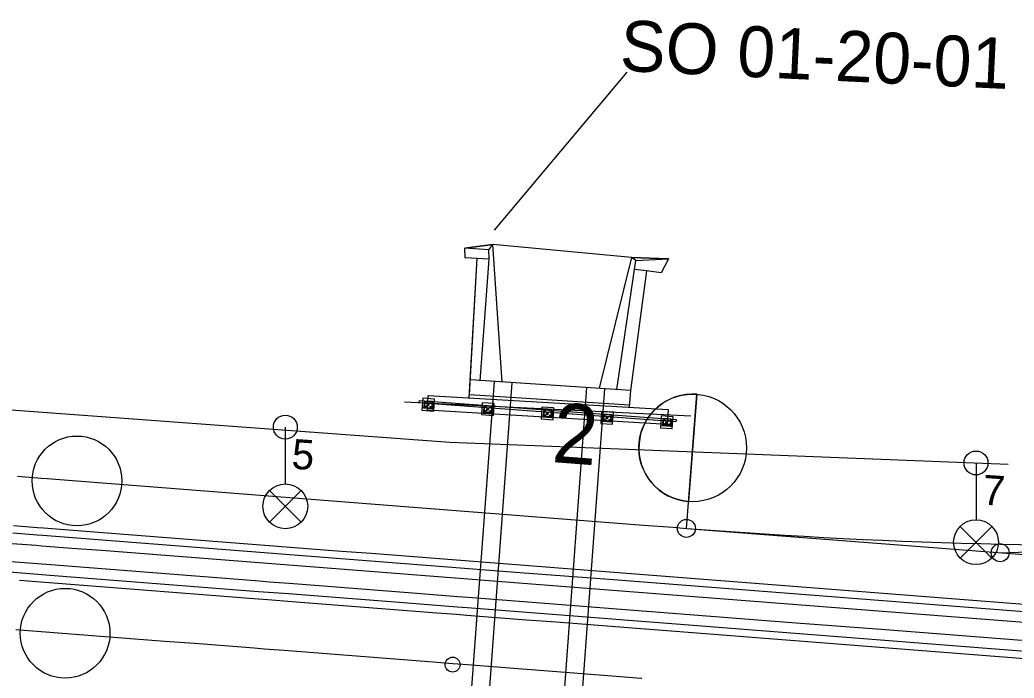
# Model space of a CAD drawing. Extents: x -669628 to -669207, y -977198 to -977075.
# Drawn here: x -669490.41 to -669457.17, y -977145.94 to -977123.92 of the extents above; entities that cross this region are included whole.
import ezdxf

# ---------------------------------------------------------------- set-up
doc = ezdxf.new("R2010")
doc.units = 0
for name, color, linetype in [('_PS_SO_číslo', 7, 'Continuous'), ('SO 01-20-01', 7, 'Continuous'), ('SO 01-20-01_Demolice', 7, 'Continuous'), ('SO 01-86-01', 7, 'Continuous'), ('SO 11-10-01', 7, 'Continuous'), ('SO 11-12-01', 7, 'Continuous')]:
    doc.layers.add(name, color=color, linetype=linetype)

# ---------------------------------------------------------------- blocks, each defined once
blk = doc.blocks.new('POINT_DISPLAY')
blk.add_line((0, 0), (0, 0))

msp = doc.modelspace()

# ---------------------------------------------------------------- linework, layer by layer
at = {"layer": '_PS_SO_číslo'}
msp.add_line((-669470.117, -977125.676), (-669474.557, -977130.959), dxfattribs=at)
at = {"layer": 'SO 01-20-01'}
for p, q in [((-669475.537, -977131.559), (-669474.597, -977131.44)), ((-669474.597, -977131.44), (-669475.537, -977131.559)), ((-669474.727, -977131.621), (-669474.597, -977131.44)), ((-669474.289, -977136.037), (-669474.597, -977131.44)), ((-669469.961, -977131.873), (-669474.597, -977131.44)), ((-669475.524, -977131.878), (-669475.537, -977131.559)), ((-669475.524, -977131.878), (-669475.537, -977131.559)), ((-669474.727, -977131.621), (-669475.537, -977131.559)), ((-669474.725, -977131.927), (-669474.727, -977131.621)), ((-669475.124, -977131.902), (-669475.524, -977131.878)), ((-669475.124, -977131.902), (-669475.524, -977131.878)), ((-669475.385, -977136.563), (-669475.124, -977131.902)), ((-669475.38, -977136.467), (-669475.124, -977131.902)), ((-669474.725, -977131.927), (-669475.124, -977131.902)), ((-669475.019, -977135.992), (-669474.725, -977131.927)), ((-669469.961, -977131.873), (-669471.044, -977136.247)), ((-669469.961, -977131.873), (-669468.725, -977131.916)), ((-669469.82, -977131.972), (-669469.961, -977131.873)), ((-669468.725, -977131.916), (-669469.961, -977131.873)), ((-669469.86, -977132.27), (-669469.82, -977131.972)), ((-669469.82, -977131.972), (-669468.725, -977131.916)), ((-669468.725, -977131.916), (-669468.968, -977132.39)), ((-669468.725, -977131.916), (-669468.968, -977132.39)), ((-669470.456, -977136.286), (-669469.86, -977132.27)), ((-669469.464, -977132.323), (-669469.998, -977136.315)), ((-669469.464, -977132.323), (-669469.86, -977132.27)), ((-669468.968, -977132.39), (-669469.464, -977132.323)), ((-669468.968, -977132.39), (-669469.464, -977132.323)), ((-669475.576, -977150.04), (-669474.546, -977136.022)), ((-669469.998, -977136.315), (-669475.348, -977135.968)), ((-669474.959, -977149.839), (-669473.947, -977136.066)), ((-669470.034, -977136.814), (-669475.38, -977136.467)), ((-669472.47, -977150.083), (-669471.452, -977136.221)), ((-669471.836, -977149.643), (-669470.854, -977136.265)), ((-669469.998, -977136.315), (-669470.039, -977136.876)), ((-669476.885, -977136.673), (-669476.918, -977136.916)), ((-669476.871, -977136.689), (-669476.886, -977136.889)), ((-669476.615, -977136.693), (-669476.885, -977136.673)), ((-669476.871, -977136.689), (-669476.885, -977136.673)), ((-669476.631, -977136.707), (-669476.871, -977136.689)), ((-669476.854, -977136.731), (-669476.814, -977136.734)), ((-669476.844, -977136.872), (-669476.841, -977136.832)), ((-669476.835, -977136.752), (-669476.832, -977136.712)), ((-669476.795, -977136.755), (-669476.801, -977136.835)), ((-669476.719, -977136.801), (-669476.798, -977136.795)), ((-669476.716, -977136.761), (-669476.795, -977136.755)), ((-669476.788, -977136.768), (-669476.793, -977136.827)), ((-669476.724, -977136.768), (-669476.783, -977136.764)), ((-669476.756, -977136.758), (-669476.761, -977136.838)), ((-669476.694, -977136.742), (-669476.654, -977136.745)), ((-669476.676, -977136.764), (-669476.673, -977136.724)), ((-669476.631, -977136.707), (-669476.646, -977136.906)), ((-669476.631, -977136.707), (-669476.615, -977136.693)), ((-669476.615, -977136.693), (-669476.618, -977136.938)), ((-669474.89, -977136.82), (-669474.923, -977137.063)), ((-669474.621, -977136.839), (-669474.89, -977136.82)), ((-669474.876, -977136.836), (-669474.89, -977136.82)), ((-669476.886, -977136.889), (-669476.918, -977136.916)), ((-669476.618, -977136.938), (-669476.918, -977136.916)), ((-669476.646, -977136.906), (-669476.886, -977136.889)), ((-669476.863, -977136.85), (-669476.823, -977136.853)), ((-669476.703, -977136.862), (-669476.663, -977136.865)), ((-669476.685, -977136.883), (-669476.682, -977136.843)), ((-669476.646, -977136.906), (-669476.618, -977136.938)), ((-669474.891, -977137.035), (-669474.923, -977137.063)), ((-669474.624, -977137.085), (-669474.923, -977137.063)), ((-669474.876, -977136.836), (-669474.891, -977137.035)), ((-669474.652, -977137.053), (-669474.891, -977137.035)), ((-669474.637, -977136.853), (-669474.876, -977136.836)), ((-669474.868, -977136.997), (-669474.828, -977137)), ((-669474.859, -977136.877), (-669474.819, -977136.88)), ((-669474.85, -977137.018), (-669474.847, -977136.978)), ((-669474.841, -977136.899), (-669474.838, -977136.859)), ((-669474.801, -977136.901), (-669474.807, -977136.981)), ((-669474.724, -977136.947), (-669474.804, -977136.941)), ((-669474.721, -977136.907), (-669474.801, -977136.901)), ((-669474.794, -977136.915), (-669474.798, -977136.974)), ((-669474.73, -977136.915), (-669474.788, -977136.91)), ((-669474.761, -977136.904), (-669474.767, -977136.984)), ((-669474.708, -977137.009), (-669474.669, -977137.011)), ((-669474.7, -977136.889), (-669474.66, -977136.892)), ((-669474.69, -977137.03), (-669474.687, -977136.99)), ((-669474.681, -977136.91), (-669474.678, -977136.87)), ((-669474.637, -977136.853), (-669474.652, -977137.053)), ((-669474.652, -977137.053), (-669474.624, -977137.085)), ((-669474.637, -977136.853), (-669474.621, -977136.839)), ((-669474.621, -977136.839), (-669474.624, -977137.085)), ((-669472.895, -977136.966), (-669472.928, -977137.209)), ((-669472.882, -977136.982), (-669472.896, -977137.182)), ((-669472.626, -977136.986), (-669472.895, -977136.966)), ((-669472.882, -977136.982), (-669472.895, -977136.966)), ((-669472.642, -977137), (-669472.882, -977136.982)), ((-669472.873, -977137.143), (-669472.833, -977137.146)), ((-669472.865, -977137.024), (-669472.825, -977137.027)), ((-669472.855, -977137.165), (-669472.852, -977137.125)), ((-669472.846, -977137.045), (-669472.843, -977137.005)), ((-669472.806, -977137.048), (-669472.812, -977137.128)), ((-669472.729, -977137.094), (-669472.809, -977137.088)), ((-669472.726, -977137.054), (-669472.806, -977137.048)), ((-669472.799, -977137.062), (-669472.804, -977137.12)), ((-669472.735, -977137.061), (-669472.794, -977137.057)), ((-669472.766, -977137.051), (-669472.772, -977137.131)), ((-669472.714, -977137.155), (-669472.674, -977137.158)), ((-669472.705, -977137.035), (-669472.665, -977137.038)), ((-669472.695, -977137.176), (-669472.692, -977137.137)), ((-669472.687, -977137.057), (-669472.684, -977137.017)), ((-669472.642, -977137), (-669472.657, -977137.199)), ((-669472.642, -977137), (-669472.626, -977136.986)), ((-669472.626, -977136.986), (-669472.629, -977137.231)), ((-669470.901, -977137.113), (-669470.934, -977137.356)), ((-669470.887, -977137.129), (-669470.902, -977137.328)), ((-669470.632, -977137.133), (-669470.901, -977137.113)), ((-669470.887, -977137.129), (-669470.901, -977137.113)), ((-669470.648, -977137.146), (-669470.887, -977137.129)), ((-669470.851, -977137.192), (-669470.849, -977137.152)), ((-669470.692, -977137.203), (-669470.689, -977137.163)), ((-669470.648, -977137.146), (-669470.662, -977137.346)), ((-669470.648, -977137.146), (-669470.632, -977137.133)), ((-669470.632, -977137.133), (-669470.635, -977137.378)), ((-669472.896, -977137.182), (-669472.928, -977137.209)), ((-669472.629, -977137.231), (-669472.928, -977137.209)), ((-669472.657, -977137.199), (-669472.896, -977137.182)), ((-669472.657, -977137.199), (-669472.629, -977137.231)), ((-669470.902, -977137.328), (-669470.934, -977137.356)), ((-669470.635, -977137.378), (-669470.934, -977137.356)), ((-669470.662, -977137.346), (-669470.902, -977137.328)), ((-669470.879, -977137.29), (-669470.839, -977137.293)), ((-669470.87, -977137.17), (-669470.83, -977137.173)), ((-669470.86, -977137.311), (-669470.857, -977137.271)), ((-669470.812, -977137.195), (-669470.817, -977137.274)), ((-669470.735, -977137.24), (-669470.815, -977137.234)), ((-669470.732, -977137.2), (-669470.812, -977137.195)), ((-669470.805, -977137.208), (-669470.809, -977137.267)), ((-669470.74, -977137.208), (-669470.799, -977137.203)), ((-669470.772, -977137.197), (-669470.778, -977137.277)), ((-669470.719, -977137.302), (-669470.679, -977137.305)), ((-669470.71, -977137.182), (-669470.67, -977137.185)), ((-669470.701, -977137.323), (-669470.698, -977137.283)), ((-669470.662, -977137.346), (-669470.635, -977137.378)), ((-669468.906, -977137.259), (-669468.939, -977137.503)), ((-669468.907, -977137.475), (-669468.939, -977137.503)), ((-669468.892, -977137.275), (-669468.907, -977137.475)), ((-669468.668, -977137.492), (-669468.907, -977137.475)), ((-669468.637, -977137.279), (-669468.906, -977137.259)), ((-669468.892, -977137.275), (-669468.906, -977137.259)), ((-669468.653, -977137.293), (-669468.892, -977137.275)), ((-669468.884, -977137.436), (-669468.844, -977137.439)), ((-669468.875, -977137.317), (-669468.835, -977137.32)), ((-669468.866, -977137.458), (-669468.863, -977137.418)), ((-669468.857, -977137.338), (-669468.854, -977137.298)), ((-669468.817, -977137.341), (-669468.823, -977137.421)), ((-669468.74, -977137.387), (-669468.82, -977137.381)), ((-669468.737, -977137.347), (-669468.817, -977137.341)), ((-669468.81, -977137.355), (-669468.814, -977137.413)), ((-669468.746, -977137.354), (-669468.805, -977137.35)), ((-669468.777, -977137.344), (-669468.783, -977137.424)), ((-669468.725, -977137.448), (-669468.685, -977137.451)), ((-669468.716, -977137.328), (-669468.676, -977137.331)), ((-669468.706, -977137.47), (-669468.703, -977137.43)), ((-669468.697, -977137.35), (-669468.694, -977137.31)), ((-669468.653, -977137.293), (-669468.668, -977137.492)), ((-669468.668, -977137.492), (-669468.64, -977137.525)), ((-669468.653, -977137.293), (-669468.637, -977137.279)), ((-669468.637, -977137.279), (-669468.64, -977137.525)), ((-669468.64, -977137.525), (-669468.939, -977137.503))]:
    msp.add_line(p, q, dxfattribs=at)
for points in [[(-669477.049, -977136.656), (-669468.472, -977137.286), (-669468.478, -977137.366), (-669477.055, -977136.736)], [(-669476.544, -977136.611), (-669476.943, -977136.581), (-669476.972, -977136.98), (-669476.574, -977137.01)], [(-669474.55, -977136.757), (-669474.949, -977136.728), (-669474.978, -977137.127), (-669474.579, -977137.156)], [(-669472.555, -977136.904), (-669472.954, -977136.874), (-669472.983, -977137.273), (-669472.584, -977137.303)], [(-669470.56, -977137.05), (-669470.959, -977137.021), (-669470.989, -977137.42), (-669470.59, -977137.449)], [(-669468.566, -977137.197), (-669468.965, -977137.168), (-669468.994, -977137.566), (-669468.595, -977137.596)]]:
    msp.add_lwpolyline(points, close=True, dxfattribs=at)
for centre in [(-669476.834, -977136.732), (-669476.674, -977136.744), (-669476.843, -977136.852), (-669476.683, -977136.863), (-669474.848, -977136.998), (-669474.839, -977136.879), (-669474.688, -977137.01), (-669474.68, -977136.89), (-669472.853, -977137.145), (-669472.845, -977137.025), (-669472.694, -977137.157), (-669472.685, -977137.037), (-669470.85, -977137.172), (-669470.859, -977137.291), (-669470.699, -977137.303), (-669470.69, -977137.183), (-669468.864, -977137.438), (-669468.855, -977137.318), (-669468.705, -977137.45), (-669468.696, -977137.33)]:
    msp.add_circle(centre, 0.01, dxfattribs=at)
for centre, radius, start, end in [((-669476.801, -977136.827), 0.008, 265.7861, 355.7984), ((-669476.783, -977136.769), 0.005, 85.7984, 175.7984), ((-669476.724, -977136.76), 0.008, 265.7861, 355.7984), ((-669474.806, -977136.973), 0.008, 265.7861, 355.7984), ((-669474.789, -977136.915), 0.005, 85.7984, 175.7984), ((-669474.729, -977136.907), 0.008, 265.7861, 355.7984), ((-669472.811, -977137.12), 0.008, 265.7861, 355.7984), ((-669472.794, -977137.062), 0.005, 85.7984, 175.7984), ((-669472.734, -977137.053), 0.008, 265.7861, 355.7984), ((-669470.817, -977137.266), 0.008, 265.7861, 355.7984), ((-669470.8, -977137.208), 0.005, 85.7984, 175.7984), ((-669470.74, -977137.2), 0.008, 265.7861, 355.7984), ((-669468.822, -977137.413), 0.008, 265.7861, 355.7984), ((-669468.805, -977137.355), 0.005, 85.7984, 175.7984), ((-669468.745, -977137.346), 0.008, 265.7861, 355.7984)]:
    msp.add_arc(centre, radius, start, end, dxfattribs=at)
at = {"layer": 'SO 01-20-01_Demolice'}
for p, q in [((-669476.785, -977136.981), (-669476.756, -977136.482)), ((-669476.756, -977136.482), (-669468.736, -977136.955)), ((-669477.549, -977136.696), (-669467.971, -977137.168)), ((-669468.765, -977137.454), (-669476.785, -977136.981)), ((-669468.736, -977136.955), (-669468.765, -977137.454))]:
    msp.add_line(p, q, dxfattribs=at)
at = {"layer": 'SO 01-86-01'}
for p, q in [((-669492.657, -977136.821), (-669476.036, -977138.048)), ((-669481.536, -977137.544), (-669481.536, -977139.044)), ((-669481.536, -977137.944), (-669481.536, -977139.444)), ((-669476.036, -977138.048), (-669457.361, -977138.783)), ((-669458.44, -977138.744), (-669458.44, -977140.244)), ((-669458.44, -977139.144), (-669458.44, -977140.644)), ((-669482.067, -977139.664), (-669481.006, -977140.724)), ((-669481.006, -977139.664), (-669482.067, -977140.724)), ((-669481.536, -977140.944), (-669481.536, -977140.944)), ((-669458.971, -977140.864), (-669457.91, -977141.924)), ((-669457.91, -977140.864), (-669458.971, -977141.924)), ((-669458.44, -977142.144), (-669458.44, -977142.144))]:
    msp.add_line(p, q, dxfattribs=at)
for centre, radius in [((-669481.536, -977137.544), 0.4), ((-669458.44, -977138.744), 0.4), ((-669481.536, -977140.194), 0.75), ((-669458.44, -977141.394), 0.75)]:
    msp.add_circle(centre, radius, dxfattribs=at)
at = {"layer": 'SO 11-10-01'}
for p, q in [((-669468.123, -977140.931), (-669467.774, -977136.444)), ((-669490.497, -977139.189), (-669489.692, -977139.252)), ((-669489.692, -977139.252), (-669489.5, -977139.267)), ((-669489.5, -977139.267), (-669488.503, -977139.344)), ((-669488.503, -977139.344), (-669487.506, -977139.422)), ((-669487.506, -977139.422), (-669486.509, -977139.5)), ((-669486.509, -977139.5), (-669485.512, -977139.577)), ((-669485.512, -977139.577), (-669484.515, -977139.655)), ((-669484.515, -977139.655), (-669483.518, -977139.732)), ((-669483.518, -977139.732), (-669482.521, -977139.81)), ((-669482.521, -977139.81), (-669481.525, -977139.888)), ((-669481.525, -977139.888), (-669480.528, -977139.965)), ((-669480.528, -977139.965), (-669479.531, -977140.043)), ((-669479.531, -977140.043), (-669478.534, -977140.12)), ((-669478.534, -977140.12), (-669477.537, -977140.198)), ((-669477.537, -977140.198), (-669476.54, -977140.276)), ((-669476.54, -977140.276), (-669475.543, -977140.353)), ((-669475.543, -977140.353), (-669474.546, -977140.431)), ((-669474.546, -977140.431), (-669473.549, -977140.508)), ((-669473.549, -977140.508), (-669472.552, -977140.586)), ((-669472.552, -977140.586), (-669471.555, -977140.664)), ((-669471.555, -977140.664), (-669470.558, -977140.741)), ((-669470.558, -977140.741), (-669469.561, -977140.819)), ((-669469.561, -977140.819), (-669468.564, -977140.896)), ((-669468.564, -977140.896), (-669468.123, -977140.931)), ((-669468.123, -977140.931), (-669441.067, -977143.037)), ((-669457.632, -977141.747), (-669441.026, -977141.2)), ((-669490.553, -977144.31), (-669489.556, -977144.388)), ((-669489.556, -977144.388), (-669488.559, -977144.465)), ((-669488.559, -977144.465), (-669487.562, -977144.543)), ((-669487.562, -977144.543), (-669486.565, -977144.621)), ((-669486.565, -977144.621), (-669485.568, -977144.698)), ((-669485.568, -977144.698), (-669484.571, -977144.776)), ((-669484.571, -977144.776), (-669483.574, -977144.853)), ((-669483.574, -977144.853), (-669482.577, -977144.931)), ((-669482.577, -977144.931), (-669482.246, -977144.957)), ((-669482.246, -977144.957), (-669481.58, -977145.009)), ((-669481.58, -977145.009), (-669480.583, -977145.086)), ((-669480.583, -977145.086), (-669479.586, -977145.164)), ((-669479.586, -977145.164), (-669478.589, -977145.241)), ((-669478.589, -977145.241), (-669477.592, -977145.319)), ((-669477.592, -977145.319), (-669476.595, -977145.397)), ((-669476.595, -977145.397), (-669475.939, -977145.448)), ((-669475.939, -977145.448), (-669475.598, -977145.474)), ((-669475.598, -977145.474), (-669474.601, -977145.552)), ((-669474.601, -977145.552), (-669473.604, -977145.63)), ((-669473.604, -977145.63), (-669472.607, -977145.707)), ((-669472.607, -977145.707), (-669471.61, -977145.785)), ((-669471.61, -977145.785), (-669470.613, -977145.862)), ((-669470.613, -977145.862), (-669469.632, -977145.939)), ((-669469.632, -977145.939), (-669469.616, -977145.94))]:
    msp.add_line(p, q, dxfattribs=at)
msp.add_lwpolyline([(-669467.774, -977136.444), (-669468.053, -977140.033), (-669468.053, -977140.033)], dxfattribs=at)
for centre, radius in [((-669467.914, -977138.239), 1.8), ((-669488.503, -977139.344), 1.5), ((-669468.123, -977140.931), 0.3), ((-669457.632, -977141.747), 0.3), ((-669488.9, -977144.439), 1.5), ((-669475.942, -977145.488), 0.25)]:
    msp.add_circle(centre, radius, dxfattribs=at)
for centre, radius, start, end in [((-669467.914, -977138.239), 1.8, 85.5493, 265.5478), ((-669453.379, -976951.504), 190, 265.54926, 271.88929)]:
    msp.add_arc(centre, radius, start, end, dxfattribs=at)
at = {"layer": 'SO 11-12-01'}
for p, q in [((-669490.645, -977141.083), (-669489.839, -977141.146)), ((-669490.625, -977140.834), (-669489.82, -977140.897)), ((-669489.839, -977141.146), (-669489.648, -977141.161)), ((-669489.82, -977140.897), (-669489.628, -977140.912)), ((-669489.628, -977140.912), (-669488.631, -977140.989)), ((-669488.631, -977140.989), (-669487.634, -977141.067)), ((-669487.634, -977141.067), (-669486.637, -977141.145)), ((-669486.637, -977141.145), (-669485.64, -977141.222)), ((-669490.672, -977141.432), (-669489.867, -977141.495)), ((-669489.648, -977141.161), (-669488.651, -977141.239)), ((-669488.651, -977141.239), (-669487.654, -977141.316)), ((-669487.654, -977141.316), (-669486.657, -977141.394)), ((-669486.657, -977141.394), (-669485.66, -977141.471)), ((-669485.66, -977141.471), (-669483.666, -977141.627)), ((-669485.64, -977141.222), (-669483.647, -977141.377)), ((-669483.647, -977141.377), (-669482.65, -977141.455)), ((-669482.65, -977141.455), (-669481.653, -977141.533)), ((-669489.867, -977141.495), (-669489.675, -977141.51)), ((-669489.675, -977141.51), (-669488.678, -977141.588)), ((-669488.678, -977141.588), (-669487.681, -977141.665)), ((-669487.681, -977141.665), (-669486.684, -977141.743)), ((-669486.684, -977141.743), (-669485.687, -977141.82)), ((-669485.687, -977141.82), (-669483.693, -977141.976)), ((-669483.666, -977141.627), (-669482.669, -977141.704)), ((-669482.669, -977141.704), (-669481.672, -977141.782)), ((-669481.672, -977141.782), (-669480.675, -977141.859)), ((-669481.653, -977141.533), (-669480.656, -977141.61)), ((-669480.656, -977141.61), (-669479.659, -977141.688)), ((-669479.659, -977141.688), (-669478.662, -977141.765)), ((-669478.662, -977141.765), (-669477.665, -977141.843)), ((-669491.375, -977141.989), (-669489.381, -977142.145)), ((-669489.381, -977142.145), (-669488.384, -977142.222)), ((-669483.693, -977141.976), (-669482.696, -977142.053)), ((-669482.696, -977142.053), (-669481.699, -977142.131)), ((-669481.699, -977142.131), (-669480.702, -977142.208)), ((-669480.675, -977141.859), (-669479.678, -977141.937)), ((-669479.678, -977141.937), (-669478.681, -977142.015)), ((-669478.681, -977142.015), (-669477.684, -977142.092)), ((-669477.684, -977142.092), (-669476.687, -977142.17)), ((-669477.665, -977141.843), (-669476.668, -977141.921)), ((-669476.668, -977141.921), (-669475.671, -977141.998)), ((-669475.671, -977141.998), (-669474.674, -977142.076)), ((-669474.674, -977142.076), (-669473.677, -977142.153)), ((-669473.677, -977142.153), (-669471.683, -977142.309)), ((-669491.403, -977142.338), (-669489.409, -977142.494)), ((-669488.384, -977142.222), (-669487.387, -977142.3)), ((-669487.387, -977142.3), (-669485.394, -977142.455)), ((-669485.394, -977142.455), (-669484.397, -977142.533)), ((-669480.702, -977142.208), (-669479.705, -977142.286)), ((-669479.705, -977142.286), (-669478.708, -977142.364)), ((-669478.708, -977142.364), (-669477.711, -977142.441)), ((-669477.711, -977142.441), (-669476.714, -977142.519)), ((-669476.687, -977142.17), (-669475.69, -977142.247)), ((-669475.69, -977142.247), (-669474.693, -977142.325)), ((-669474.693, -977142.325), (-669473.696, -977142.403)), ((-669473.696, -977142.403), (-669470.705, -977142.635)), ((-669471.683, -977142.309), (-669470.686, -977142.386)), ((-669470.686, -977142.386), (-669440.359, -977144.747)), ((-669490.425, -977142.665), (-669489.428, -977142.743)), ((-669489.428, -977142.743), (-669488.431, -977142.82)), ((-669489.409, -977142.494), (-669488.412, -977142.571)), ((-669488.412, -977142.571), (-669487.415, -977142.649)), ((-669487.415, -977142.649), (-669485.421, -977142.804)), ((-669485.421, -977142.804), (-669484.424, -977142.882)), ((-669484.397, -977142.533), (-669482.403, -977142.688)), ((-669482.403, -977142.688), (-669482.072, -977142.714)), ((-669482.072, -977142.714), (-669481.406, -977142.765)), ((-669481.406, -977142.765), (-669480.409, -977142.843)), ((-669476.714, -977142.519), (-669475.717, -977142.596)), ((-669475.717, -977142.596), (-669474.72, -977142.674)), ((-669474.72, -977142.674), (-669473.723, -977142.752)), ((-669473.723, -977142.752), (-669470.732, -977142.984)), ((-669470.705, -977142.635), (-669440.379, -977144.996)), ((-669488.431, -977142.82), (-669487.434, -977142.898)), ((-669487.434, -977142.898), (-669486.437, -977142.976)), ((-669486.437, -977142.976), (-669485.44, -977143.053)), ((-669485.44, -977143.053), (-669484.443, -977143.131)), ((-669484.443, -977143.131), (-669483.446, -977143.208)), ((-669484.424, -977142.882), (-669482.43, -977143.037)), ((-669482.43, -977143.037), (-669482.099, -977143.063)), ((-669482.099, -977143.063), (-669481.433, -977143.114)), ((-669481.433, -977143.114), (-669480.436, -977143.192)), ((-669480.409, -977142.843), (-669479.412, -977142.921)), ((-669479.412, -977142.921), (-669478.415, -977142.998)), ((-669478.415, -977142.998), (-669477.418, -977143.076)), ((-669477.418, -977143.076), (-669475.765, -977143.205)), ((-669470.732, -977142.984), (-669440.406, -977145.345)), ((-669483.446, -977143.208), (-669482.449, -977143.286)), ((-669482.449, -977143.286), (-669482.118, -977143.312)), ((-669482.118, -977143.312), (-669481.452, -977143.364)), ((-669481.452, -977143.364), (-669480.455, -977143.441)), ((-669480.455, -977143.441), (-669479.458, -977143.519)), ((-669480.436, -977143.192), (-669479.439, -977143.27)), ((-669479.439, -977143.27), (-669478.442, -977143.347)), ((-669478.442, -977143.347), (-669477.445, -977143.425)), ((-669477.445, -977143.425), (-669475.792, -977143.554)), ((-669475.765, -977143.205), (-669475.424, -977143.231)), ((-669475.424, -977143.231), (-669474.427, -977143.309)), ((-669474.427, -977143.309), (-669473.43, -977143.386)), ((-669473.43, -977143.386), (-669472.433, -977143.464)), ((-669472.433, -977143.464), (-669469.458, -977143.696)), ((-669479.458, -977143.519), (-669478.461, -977143.596)), ((-669478.461, -977143.596), (-669477.464, -977143.674)), ((-669477.464, -977143.674), (-669476.467, -977143.752)), ((-669476.467, -977143.752), (-669475.811, -977143.803)), ((-669475.811, -977143.803), (-669475.47, -977143.829)), ((-669475.792, -977143.554), (-669475.451, -977143.58)), ((-669475.451, -977143.58), (-669474.454, -977143.658)), ((-669474.454, -977143.658), (-669473.457, -977143.735)), ((-669473.457, -977143.735), (-669472.46, -977143.813)), ((-669472.46, -977143.813), (-669469.485, -977144.044)), ((-669469.458, -977143.696), (-669469.442, -977143.697)), ((-669469.442, -977143.697), (-669468.445, -977143.774)), ((-669468.445, -977143.774), (-669467.448, -977143.852)), ((-669475.47, -977143.829), (-669474.473, -977143.907)), ((-669474.473, -977143.907), (-669473.476, -977143.985)), ((-669473.476, -977143.985), (-669472.479, -977144.062)), ((-669472.479, -977144.062), (-669471.482, -977144.14)), ((-669471.482, -977144.14), (-669469.504, -977144.294)), ((-669469.485, -977144.044), (-669469.469, -977144.046)), ((-669469.469, -977144.046), (-669468.472, -977144.123)), ((-669468.472, -977144.123), (-669467.475, -977144.201)), ((-669467.448, -977143.852), (-669466.451, -977143.93)), ((-669466.451, -977143.93), (-669465.454, -977144.007)), ((-669465.454, -977144.007), (-669464.457, -977144.085)), ((-669464.457, -977144.085), (-669461.466, -977144.318)), ((-669469.504, -977144.294), (-669469.488, -977144.295)), ((-669469.488, -977144.295), (-669468.491, -977144.373)), ((-669468.491, -977144.373), (-669467.494, -977144.45)), ((-669467.494, -977144.45), (-669466.497, -977144.528)), ((-669467.475, -977144.201), (-669466.478, -977144.278)), ((-669466.478, -977144.278), (-669465.481, -977144.356)), ((-669465.481, -977144.356), (-669464.484, -977144.434)), ((-669464.484, -977144.434), (-669461.493, -977144.667)), ((-669461.466, -977144.318), (-669460.469, -977144.395)), ((-669460.469, -977144.395), (-669459.472, -977144.473)), ((-669459.472, -977144.473), (-669458.475, -977144.55)), ((-669466.497, -977144.528), (-669465.5, -977144.605)), ((-669465.5, -977144.605), (-669464.503, -977144.683)), ((-669464.503, -977144.683), (-669461.512, -977144.916)), ((-669461.493, -977144.667), (-669460.496, -977144.744)), ((-669460.496, -977144.744), (-669459.499, -977144.822)), ((-669458.475, -977144.55), (-669457.478, -977144.628)), ((-669457.478, -977144.628), (-669456.481, -977144.706)), ((-669461.512, -977144.916), (-669460.515, -977144.993)), ((-669460.515, -977144.993), (-669459.518, -977145.071)), ((-669459.518, -977145.071), (-669458.521, -977145.149)), ((-669459.499, -977144.822), (-669458.502, -977144.899)), ((-669458.502, -977144.899), (-669457.505, -977144.977)), ((-669457.505, -977144.977), (-669456.508, -977145.055)), ((-669458.521, -977145.149), (-669457.525, -977145.226)), ((-669457.525, -977145.226), (-669456.528, -977145.304))]:
    msp.add_line(p, q, dxfattribs=at)

# ---------------------------------------------------------------- block references
at = {"layer": 'SO 01-86-01', "rotation": 4.450857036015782}
for p in [(-669481.566, -977137.56), (-669458.47, -977138.76)]:
    msp.add_blockref('POINT_DISPLAY', p, dxfattribs=at)
at = {"layer": 'SO 11-10-01'}
msp.add_blockref('POINT_DISPLAY', (-669468.123, -977140.931), dxfattribs=at)
msp.add_blockref('POINT_DISPLAY', (-669468.123, -977140.931), dxfattribs=at)

# ---------------------------------------------------------------- texts
at = {"layer": '_PS_SO_číslo'}
msp.add_text('SO 01-20-01', height=1.7, rotation=357.3, dxfattribs=at).set_placement((-669470.368, -977125.625))
at = {"layer": 'SO 01-86-01'}
for s, p in [('5', (-669481.345, -977138.934)), ('7', (-669458.249, -977140.134))]:
    msp.add_text(s, height=1, rotation=356.1, dxfattribs=at).set_placement(p)
at = {"layer": 'SO 11-10-01'}
msp.add_text('2', height=2, rotation=355.5464, dxfattribs=at).set_placement((-669472.649, -977138.71))

doc.saveas('drawing.dxf')
